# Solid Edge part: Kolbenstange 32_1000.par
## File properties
Username: ahadarics
Dokumentum tartalom típus: 0
Author: ahadarics
Last saved by: ahadarics
Revision: 94
Sűrűség: 0,000 kg/m^3
Pontosság: 0,990
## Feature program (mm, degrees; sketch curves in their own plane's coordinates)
base feature "unnamed BaseFeature 1"
thread "unnamed Thread 1"
chamfer "Letörés_1"  SetBackValue2 = 20 deg
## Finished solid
Body 1: solid body, 19 faces, 27 edges, 11 vertices.
  Faces by surface: plane 8, cylinder 5, cone 3, torus 3
  Edges by curve: circle 15, line 7, curve on surface 3, ellipse 2
Bounding box of the edges (mm; curved faces can reach further): 32.000 x 32.000 x 1115.500, from (-16, -16, -50.25) to (16, 16, 1065.25).
Cylindrical faces by radius (mm): R3.95 x1, R5 x1, R5.8 x1, R6 x1, R16 x1
Conical faces (half-angle, radius in mm at the cone's reference point): 20 deg R5 x1, 30 deg R5.9 x1, 60 deg R4.475 x1
Toroidal faces (ring radius, tube radius in mm): R4.35 r0.4 x2, R4.6 r1.2 x1
Planar faces by outward normal: +x 1, +z 3, -x 1, -z 1, oblique 2
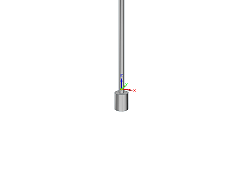
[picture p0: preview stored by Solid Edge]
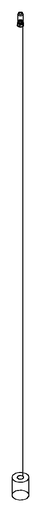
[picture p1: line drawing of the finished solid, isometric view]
